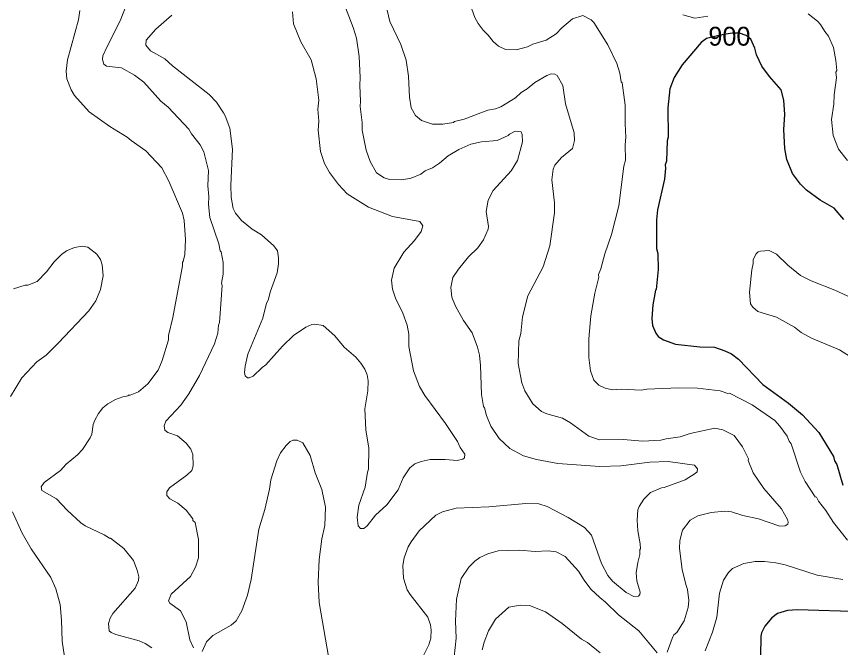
# Model space of a CAD drawing. Extents: x 265.7 to 292.1, y 7676.2 to 7704.2.
# Drawn here: x 276.42 to 279.917, y 7683.888 to 7686.563 of the extents above; entities that cross this region are included whole.
import ezdxf
from ezdxf.enums import TextEntityAlignment as Align

# ---------------------------------------------------------------- set-up
doc = ezdxf.new("R2010")
doc.units = 0
doc.header["$LTSCALE"] = 0.032
doc.layers.add('1', color=7, linetype='Continuous', lineweight=25)
doc.layers.add('2', color=7, linetype='Continuous', lineweight=13)
doc.layers.add('61', color=7, linetype='Continuous')

msp = doc.modelspace()

# ---------------------------------------------------------------- linework, layer by layer
at = {"layer": '1'}
for points in [[(279.9314, 7685.7024), (279.8899, 7685.7502), (279.8308, 7685.7845), (279.7726, 7685.8268), (279.7478, 7685.8516), (279.7135, 7685.8971), (279.6888, 7685.9561), (279.6808, 7686.004), (279.6768, 7686.0838), (279.6808, 7686.1476), (279.6768, 7686.2083), (279.6648, 7686.2514), (279.6162, 7686.308), (279.5834, 7686.3527), (279.5611, 7686.3998), (279.5531, 7686.4285), (279.5361, 7686.4673), (279.5172, 7686.4824), (279.489, 7686.4918), (279.4569, 7686.4918), (279.406, 7686.4843), (279.3476, 7686.4692), (279.325, 7686.4522), (279.2451, 7686.3583), (279.2108, 7686.304), (279.1924, 7686.2561), (279.1845, 7686.1763), (279.1853, 7686.0519), (279.1813, 7686.0359), (279.1781, 7685.9497), (279.1733, 7685.9338), (279.1749, 7685.9194), (279.1701, 7685.8731), (279.1398, 7685.7438), (279.1358, 7685.7008), (279.1366, 7685.5795), (279.1414, 7685.5587), (279.143, 7685.4901), (279.135, 7685.4055), (279.1318, 7685.4031), (279.1206, 7685.3401), (279.1158, 7685.2826), (279.119, 7685.2523), (279.1334, 7685.2204), (279.1438, 7685.206), (279.1653, 7685.1924), (279.2164, 7685.1741), (279.3201, 7685.1629), (279.3824, 7685.1605), (279.4255, 7685.1462), (279.4542, 7685.1326), (279.4837, 7685.1103), (279.5874, 7685.0025), (279.6968, 7684.9235), (279.755, 7684.8741), (279.8244, 7684.7991), (279.8867, 7684.6977), (279.8915, 7684.6794), (279.901, 7684.6634), (279.9274, 7684.5756)], [(280.008, 7684.0386), (279.7351, 7684.0474), (279.692, 7684.0442), (279.6489, 7684.0314), (279.625, 7684.0139), (279.5954, 7683.9788), (279.5818, 7683.95), (279.5787, 7683.9357), (279.5771, 7683.8495)]]:
    msp.add_lwpolyline(points, dxfattribs=at)
at = {"layer": '2'}
for points in [[(276.9606, 7686.2841), (276.9207, 7686.3144), (276.8664, 7686.3447), (276.8018, 7686.3527), (276.7906, 7686.3615), (276.7858, 7686.3806), (276.7874, 7686.3958), (276.8049, 7686.4365), (276.86, 7686.545), (276.8991, 7686.6439)], [(277.8056, 7686.6312), (277.8495, 7686.5163), (277.863, 7686.4716), (277.875, 7686.3934), (277.879, 7686.304), (277.8774, 7686.2705), (277.8806, 7686.2035), (277.8782, 7686.1811), (277.8878, 7686.1141), (277.8878, 7686.0806), (277.9045, 7685.996), (277.9205, 7685.9481), (277.9476, 7685.9002), (277.9812, 7685.8787), (278.0035, 7685.8715), (278.0562, 7685.8699), (278.0945, 7685.8771), (278.136, 7685.8947), (278.1551, 7685.9082), (278.1862, 7685.9218), (278.2158, 7685.9417), (278.2525, 7685.9729), (278.2971, 7685.9992), (278.3482, 7686.0223), (278.3929, 7686.0319), (278.4599, 7686.0367), (278.507, 7686.0582), (278.5118, 7686.0646), (278.5365, 7686.0766), (278.5621, 7686.0734), (278.5661, 7686.063), (278.5676, 7686.0311), (278.5469, 7685.9529), (278.519, 7685.9082)], [(278.3314, 7686.6551), (278.365, 7686.5594), (278.3793, 7686.533), (278.4009, 7686.5051), (278.4216, 7686.4844), (278.4424, 7686.4572), (278.4663, 7686.4373), (278.495, 7686.4237), (278.5413, 7686.4213), (278.5892, 7686.4341), (278.6115, 7686.4452), (278.6674, 7686.462), (278.7105, 7686.4891), (278.7344, 7686.5155), (278.7791, 7686.553), (278.8238, 7686.5673), (278.8589, 7686.5482), (278.8709, 7686.5378), (278.9299, 7686.4429), (278.9682, 7686.3631), (278.981, 7686.3232), (278.9858, 7686.2857), (278.9898, 7686.2817), (279.0025, 7686.1875), (279.0025, 7686.1077), (279.0065, 7686.0519), (279.0033, 7686.0183), (279.0041, 7685.9545), (278.9977, 7685.929), (278.9762, 7685.7598), (278.9451, 7685.6385), (278.9164, 7685.5571), (278.8996, 7685.4933), (278.89, 7685.4685), (278.8908, 7685.4574), (278.8741, 7685.3896), (278.8573, 7685.2938), (278.8485, 7685.1964), (278.8485, 7685.1166), (278.8557, 7685.0608), (278.8709, 7685.0209), (278.8916, 7684.9993), (278.918, 7684.9866), (278.9499, 7684.9802), (278.9866, 7684.9826), (279.0712, 7684.9794), (279.0951, 7684.9834), (279.2308, 7684.989), (279.3106, 7684.9866), (279.4063, 7684.9754), (279.4382, 7684.965), (279.4454, 7684.9658), (279.542, 7684.9164)], [(276.8289, 7684.0314), (276.9238, 7684.1399), (276.9374, 7684.1719), (276.939, 7684.1878), (276.9326, 7684.215), (276.9167, 7684.2564), (276.876, 7684.3075), (276.8193, 7684.3514), (276.8145, 7684.3514), (276.7922, 7684.3658), (276.7124, 7684.4041), (276.694, 7684.4168), (276.6358, 7684.4695), (276.5895, 7684.5174), (276.5281, 7684.5541), (276.5257, 7684.5692), (276.5384, 7684.5868), (276.6071, 7684.6379), (276.6318, 7684.665), (276.6789, 7684.7041), (276.7004, 7684.7272), (276.7331, 7684.7767), (276.7395, 7684.7927), (276.7459, 7684.8326), (276.7523, 7684.8517), (276.7682, 7684.8805), (276.7874, 7684.9036), (276.8073, 7684.9211), (276.8401, 7684.9395), (276.872, 7684.9507), (276.8943, 7684.9547), (276.8943, 7684.9578), (276.9023, 7684.9578), (276.9382, 7684.9722), (276.9781, 7685.0057), (277.0212, 7685.064), (277.0388, 7685.1039), (277.0651, 7685.1917), (277.0651, 7685.2108), (277.0842, 7685.2874), (277.1249, 7685.506), (277.1241, 7685.522), (277.1281, 7685.5244), (277.1345, 7685.5539), (277.1377, 7685.6178), (277.1313, 7685.6976), (277.1241, 7685.7295), (277.0667, 7685.8651), (277.0364, 7685.921), (276.9685, 7685.9936), (276.9071, 7686.0367), (276.8903, 7686.0519), (276.8161, 7686.0965), (276.7283, 7686.1588), (276.6661, 7686.2274), (276.6525, 7686.2514), (276.6334, 7686.2992), (276.6318, 7686.3311), (276.6366, 7686.379), (276.6829, 7686.5482), (276.6892, 7686.5881)], [(277.9931, 7686.5897), (278.0043, 7686.5418), (278.0514, 7686.4445), (278.0737, 7686.3774), (278.0841, 7686.3104), (278.0881, 7686.221), (278.0953, 7686.1763), (278.1136, 7686.1428), (278.1391, 7686.1221), (278.1854, 7686.1069), (278.2301, 7686.1061), (278.2748, 7686.1133), (278.2796, 7686.1173), (278.3195, 7686.1277), (278.42, 7686.166), (278.4535, 7686.1715), (278.4759, 7686.1795), (278.5381, 7686.2178), (278.5621, 7686.2402), (278.5876, 7686.2561), (278.6195, 7686.2833), (278.6706, 7686.3128), (278.6897, 7686.32), (278.7041, 7686.3192), (278.7153, 7686.3128), (278.7384, 7686.2705), (278.7504, 7686.1923), (278.7863, 7686.0694), (278.7879, 7686.0375), (278.7799, 7686.004), (278.7336, 7685.9649), (278.7049, 7685.9322), (278.6977, 7685.9162), (278.6921, 7685.8699), (278.7033, 7685.7726), (278.7033, 7685.7311), (278.6841, 7685.5906), (278.6554, 7685.5013), (278.59, 7685.3784), (278.5676, 7685.289), (278.5605, 7685.2188)], [(277.2981, 7686.154), (277.2694, 7686.2003), (277.2382, 7686.2322), (277.0826, 7686.3543), (277.0499, 7686.3838), (276.9885, 7686.4173), (276.9693, 7686.4413), (276.9701, 7686.462), (277.0116, 7686.5099), (277.0795, 7686.5681)], [(277.5917, 7686.5833), (277.5965, 7686.5322), (277.6268, 7686.4556), (277.6707, 7686.379), (277.6915, 7686.2992), (277.7035, 7686.2083), (277.6995, 7686.17), (277.7027, 7686.1189), (277.7003, 7686.0806), (277.7098, 7685.9912), (277.7274, 7685.9401), (277.7481, 7685.9018), (277.7864, 7685.8508), (277.8231, 7685.8109), (277.9141, 7685.7542), (278.0163, 7685.7151), (278.1312, 7685.6944), (278.1447, 7685.676), (278.1375, 7685.6513), (278.1096, 7685.613), (278.0641, 7685.5635), (278.0226, 7685.4965), (278.0123, 7685.4454), (278.0155, 7685.4071), (278.0282, 7685.3688), (278.0601, 7685.305), (278.0777, 7685.2539), (278.0857, 7685.2156), (278.0857, 7685.1645)], [(279.3536, 7686.5649), (279.2994, 7686.5554), (279.2475, 7686.5705)], [(279.9465, 7685.9529), (279.909, 7686.0008), (279.8851, 7686.0582), (279.8787, 7686.1269), (279.8883, 7686.1907), (279.8899, 7686.2306), (279.8994, 7686.3024), (279.8978, 7686.3264), (279.901, 7686.3335), (279.8978, 7686.3758), (279.8875, 7686.4317), (279.8667, 7686.4796), (279.8508, 7686.4987), (279.8324, 7686.529), (279.8189, 7686.5434), (279.7798, 7686.5737)], [(277.2151, 7685.9896), (277.1991, 7686.0183), (277.1624, 7686.0662), (277.1513, 7686.0854), (277.0643, 7686.1779), (277.0332, 7686.2043), (276.9606, 7686.2841)], [(278.3035, 7684.7352), (278.3227, 7684.7073), (278.3211, 7684.6913), (278.3147, 7684.6865), (278.2908, 7684.681), (278.2397, 7684.6849), (278.1759, 7684.6849), (278.1376, 7684.677), (278.1104, 7684.6666), (278.0897, 7684.6498), (278.0617, 7684.6075), (278.0402, 7684.5565), (277.9923, 7684.4926), (277.9444, 7684.4495), (277.9077, 7684.4033), (277.8942, 7684.3929), (277.8806, 7684.3921), (277.8702, 7684.4033), (277.8654, 7684.44), (277.8734, 7684.491), (277.9006, 7684.5677), (277.9093, 7684.6315), (277.9141, 7684.6443), (277.9157, 7684.7336), (277.9029, 7684.8102), (277.899, 7684.8996), (277.9117, 7684.9762), (277.9125, 7685.0177), (277.9077, 7685.0432), (277.899, 7685.0672), (277.8822, 7685.0927), (277.8599, 7685.1182), (277.8104, 7685.1605), (277.7705, 7685.2092), (277.721, 7685.2531), (277.6859, 7685.2587), (277.6731, 7685.2571), (277.6476, 7685.2459), (277.5965, 7685.21), (277.5487, 7685.1653), (277.4784, 7685.0855), (277.4625, 7685.0744), (277.425, 7685.0384), (277.4082, 7685.0305), (277.401, 7685.0305), (277.3907, 7685.0392), (277.3883, 7685.0544), (277.3907, 7685.0799), (277.4018, 7685.131), (277.4657, 7685.2842), (277.4816, 7685.3481), (277.4888, 7685.3608), (277.4984, 7685.3991), (277.5271, 7685.4757), (277.5327, 7685.514), (277.5327, 7685.5396), (277.5279, 7685.5691), (277.5127, 7685.5906), (277.4593, 7685.6377), (277.421, 7685.6617), (277.3747, 7685.6984), (277.35, 7685.7287), (277.3404, 7685.7494), (277.3316, 7685.7965), (277.3292, 7685.8476), (277.3364, 7686.0008), (277.3252, 7686.0902), (277.3061, 7686.1412), (277.2981, 7686.154)], [(277.172, 7683.8862), (277.1561, 7683.9197), (277.1401, 7683.9971), (277.117, 7684.0434), (277.0707, 7684.0753), (277.0659, 7684.0857), (277.0771, 7684.1144), (277.1585, 7684.1886), (277.18, 7684.2277), (277.1928, 7684.2676), (277.1928, 7684.3458), (277.1784, 7684.4176), (277.1688, 7684.4264), (277.1688, 7684.4328), (277.1401, 7684.4703), (277.105, 7684.4998), (277.0707, 7684.5174), (277.0587, 7684.5325), (277.0579, 7684.5477), (277.0691, 7684.5653), (277.1433, 7684.6187), (277.164, 7684.6387), (277.1704, 7684.6578), (277.1688, 7684.7065), (277.1608, 7684.7288), (277.1409, 7684.7544), (277.1034, 7684.7855), (277.0619, 7684.7999), (277.0499, 7684.8094), (277.0475, 7684.8278), (277.0539, 7684.8477), (277.1177, 7684.9156), (277.1513, 7684.9634), (277.1975, 7685.0416), (277.2606, 7685.1757), (277.2749, 7685.2204), (277.2781, 7685.2539), (277.2821, 7685.2651), (277.2925, 7685.4231), (277.2909, 7685.4326), (277.2973, 7685.4709), (277.2973, 7685.5204), (277.2893, 7685.5651), (277.2853, 7685.5691), (277.2789, 7685.5986), (277.2414, 7685.7103), (277.2351, 7685.7662), (277.2366, 7685.7997), (277.2327, 7685.8444), (277.2351, 7685.9098), (277.2151, 7685.9896)], [(278.519, 7685.9082), (278.4432, 7685.826), (278.4216, 7685.7837), (278.4136, 7685.7359), (278.4232, 7685.672), (278.4224, 7685.6609), (278.4025, 7685.6162)], [(278.4025, 7685.6162), (278.3785, 7685.5827), (278.3386, 7685.5443), (278.2955, 7685.4917), (278.2724, 7685.4566), (278.2636, 7685.4135), (278.2676, 7685.3736), (278.2836, 7685.3353), (278.3171, 7685.2746), (278.3546, 7685.2212), (278.3769, 7685.1613), (278.3849, 7685.1278), (278.3897, 7685.0831), (278.3929, 7684.9602), (278.4025, 7684.91), (278.4065, 7684.9044), (278.4144, 7684.8709), (278.4336, 7684.8262), (278.4687, 7684.7743), (278.5134, 7684.7312), (278.5716, 7684.7009), (278.6275, 7684.6849), (278.7169, 7684.6674), (278.8956, 7684.6554), (278.985, 7684.6578), (279.1079, 7684.6738), (279.1861, 7684.677), (279.2978, 7684.661), (279.3106, 7684.645), (279.3082, 7684.6331), (279.3002, 7684.6251), (279.2579, 7684.5988), (279.1685, 7684.5668), (279.1573, 7684.5653), (279.1111, 7684.5445), (279.0823, 7684.5166), (279.0632, 7684.4863), (279.0576, 7684.4711), (279.0544, 7684.4272), (279.0568, 7684.3825), (279.0672, 7684.3267), (279.068, 7684.3059), (279.0648, 7684.3027), (279.0656, 7684.282), (279.0568, 7684.2485), (279.0504, 7684.2038), (279.0528, 7684.1703), (279.0664, 7684.1224), (279.0648, 7684.1128), (279.0592, 7684.1056), (279.04, 7684.104), (279.0073, 7684.1208), (278.9499, 7684.1695), (278.9291, 7684.1926), (278.9028, 7684.2437), (278.8597, 7684.3634), (278.831, 7684.3961), (278.7616, 7684.4384), (278.6722, 7684.4855), (278.6371, 7684.4966), (278.5812, 7684.499), (278.4248, 7684.4839), (278.286, 7684.4783), (278.2285, 7684.4623), (278.1998, 7684.4487), (278.1296, 7684.3825), (278.0953, 7684.3362), (278.0825, 7684.3139), (278.0649, 7684.2684), (278.0601, 7684.2357), (278.0625, 7684.1814), (278.0785, 7684.132), (278.0905, 7684.1128), (278.1663, 7684.0163), (278.1766, 7683.9835), (278.1798, 7683.9612), (278.179, 7683.9277), (278.1703, 7683.899), (278.1367, 7683.8319)], [(276.3948, 7684.9523), (276.4427, 7685.0305), (276.5073, 7685.0983), (276.5456, 7685.1278), (276.5983, 7685.1789), (276.7275, 7685.3153), (276.7571, 7685.3576), (276.7762, 7685.4055), (276.7882, 7685.463), (276.7834, 7685.5108), (276.7762, 7685.5332), (276.7619, 7685.5555), (276.7236, 7685.585), (276.6996, 7685.589), (276.6661, 7685.5835), (276.6326, 7685.5699), (276.611, 7685.5539), (276.5807, 7685.5228), (276.548, 7685.4805), (276.5081, 7685.4398), (276.4682, 7685.4239), (276.4578, 7685.4239), (276.4076, 7685.4087)], [(279.7925, 7685.443), (279.7478, 7685.4654), (279.6928, 7685.5084), (279.6457, 7685.5547), (279.6138, 7685.5707), (279.5771, 7685.5683), (279.5675, 7685.5651), (279.5587, 7685.5571), (279.5467, 7685.5324), (279.5467, 7685.5164), (279.5404, 7685.4885), (279.5308, 7685.3943), (279.5356, 7685.3449), (279.5451, 7685.3305), (279.5667, 7685.3121), (279.6457, 7685.2882), (279.7223, 7685.2459), (279.7502, 7685.2236), (279.7941, 7685.1988), (279.9122, 7685.1502), (279.9594, 7685.1205)], [(280.2019, 7685.1693), (280.1356, 7685.2507), (280.0918, 7685.2906), (280.0167, 7685.3425), (279.9824, 7685.3616), (279.8931, 7685.4031), (279.7925, 7685.443)], [(278.5605, 7685.2188), (278.5517, 7685.1885), (278.5485, 7685.0919), (278.5645, 7685.0097), (278.578, 7684.9762), (278.6115, 7684.9204), (278.6482, 7684.8884)], [(278.0857, 7685.1645), (278.1056, 7685.0608), (278.1304, 7684.9938), (278.1527, 7684.9555), (278.2413, 7684.8374), (278.2923, 7684.7608), (278.3035, 7684.7352)], [(279.542, 7684.9164), (279.6377, 7684.8501), (279.6601, 7684.8262), (279.6912, 7684.7831), (279.6992, 7684.7624), (279.7079, 7684.7512), (279.747, 7684.6315)], [(278.6482, 7684.8884), (278.6706, 7684.8788), (278.7376, 7684.8605), (278.7711, 7684.8405), (278.8493, 7684.7839), (278.894, 7684.7679), (278.9946, 7684.7695), (279.0776, 7684.7631), (279.1542, 7684.7663), (279.1765, 7684.7727), (279.2371, 7684.7807), (279.2794, 7684.7951), (279.384, 7684.8182), (279.4175, 7684.811), (279.4654, 7684.7871), (279.5005, 7684.7384), (279.526, 7684.6881), (279.5252, 7684.681), (279.5459, 7684.6283), (279.5914, 7684.5621), (279.6664, 7684.4751), (279.692, 7684.4304), (279.6952, 7684.4192), (279.6936, 7684.4105), (279.6824, 7684.4033), (279.6601, 7684.4025), (279.5691, 7684.4328), (279.5021, 7684.4472), (279.4542, 7684.4623), (279.4255, 7684.4655), (279.368, 7684.4607), (279.3122, 7684.4456), (279.2786, 7684.4272), (279.2467, 7684.3857), (279.2347, 7684.341), (279.2331, 7684.3075), (279.2451, 7684.2181), (279.2603, 7684.1543), (279.2683, 7684.1344), (279.273, 7684.0873), (279.2707, 7684.057), (279.2531, 7684.0011), (279.2228, 7683.9508), (279.21, 7683.9412), (279.202, 7683.9261), (279.1821, 7683.8686)], [(277.7442, 7683.8495), (277.7043, 7684.0793), (277.7003, 7684.1655), (277.7043, 7684.2612), (277.7162, 7684.349), (277.7282, 7684.4049), (277.7322, 7684.4831), (277.7162, 7684.5573), (277.6883, 7684.6283), (277.6659, 7684.7017), (277.6356, 7684.7552), (277.6109, 7684.7663), (277.5949, 7684.7671), (277.5822, 7684.7608), (277.5646, 7684.744), (277.5407, 7684.7129), (277.5255, 7684.6794), (277.5, 7684.598), (277.4944, 7684.5597), (277.4744, 7684.4735), (277.4489, 7684.3889), (277.4162, 7684.1767), (277.401, 7684.1096), (277.3771, 7684.0426), (277.3523, 7684.0011), (277.3316, 7683.9827), (277.2534, 7683.9388), (277.2263, 7683.9117), (277.2079, 7683.871)], [(279.747, 7684.6315), (279.767, 7684.5916), (279.8101, 7684.527), (279.8157, 7684.5246), (279.8236, 7684.5086), (279.8548, 7684.4687), (279.8867, 7684.4176), (279.9473, 7684.3426)], [(276.6246, 7683.8479), (276.6142, 7683.9149), (276.6118, 7684.0043), (276.6055, 7684.0697), (276.5871, 7684.1368), (276.5664, 7684.1846), (276.4826, 7684.3059), (276.4443, 7684.3729), (276.4036, 7684.4623)], [(279.139, 7683.8654), (279.0608, 7683.958), (278.9754, 7684.0258), (278.9203, 7684.0801), (278.8956, 7684.0992), (278.8581, 7684.1352), (278.8286, 7684.1735), (278.8046, 7684.2118), (278.7488, 7684.2732), (278.7105, 7684.2939), (278.677, 7684.2979), (278.6211, 7684.2955), (278.5541, 7684.3003), (278.4647, 7684.2971), (278.42, 7684.2852), (278.3865, 7684.2692), (278.3658, 7684.254), (278.3394, 7684.2277), (278.3067, 7684.1798), (278.2868, 7684.0921), (278.2828, 7683.9995), (278.286, 7683.9277), (278.2772, 7683.8479)], [(279.9266, 7684.1758), (279.8181, 7684.1942), (279.6824, 7684.2381), (279.6425, 7684.2469), (279.5946, 7684.2525), (279.5547, 7684.2525), (279.5069, 7684.2437), (279.459, 7684.2221), (279.4414, 7684.2062), (279.4207, 7684.1735), (279.4031, 7684.1176), (279.3919, 7684.0171), (279.3736, 7683.9532), (279.3425, 7683.8734)], [(278.8972, 7683.8646), (278.8429, 7683.9085), (278.8182, 7683.9237), (278.736, 7683.9899), (278.665, 7684.0394), (278.5972, 7684.0665), (278.5573, 7684.0673), (278.5094, 7684.0585), (278.4535, 7684.0075), (278.4232, 7683.958), (278.4049, 7683.9101), (278.3969, 7683.8782)], [(276.9406, 7683.9157), (276.8417, 7683.9428), (276.8225, 7683.9508), (276.8129, 7683.9588), (276.8113, 7683.9891), (276.8177, 7684.0123), (276.8289, 7684.0314)], [(276.9941, 7683.887), (276.9669, 7683.9045), (276.9406, 7683.9157)]]:
    msp.add_lwpolyline(points, dxfattribs=at)

# ---------------------------------------------------------------- texts
at = {"layer": '61'}
msp.add_text('900', height=0.08, dxfattribs=at).set_placement((279.4456, 7686.4394), align=Align.CENTER)

doc.saveas('drawing.dxf')
